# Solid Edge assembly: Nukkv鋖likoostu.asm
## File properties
Author: Türk
Template: Iso Assembly.asm
Last saved by: Türk
Revision: 7
Application: Solid Edge
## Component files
ll.par
llihammasratas.par
Saalenukk.par
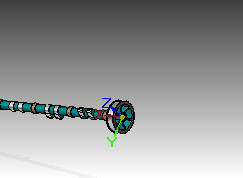
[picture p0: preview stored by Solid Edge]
